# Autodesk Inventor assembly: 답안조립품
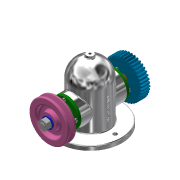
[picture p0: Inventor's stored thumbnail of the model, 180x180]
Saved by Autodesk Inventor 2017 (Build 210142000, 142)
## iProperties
Created: 2019-11
Part Number: 답안조립품
Document SubType Name: Assembly
Designer: 1-15-lg-1
Author: 1-15-lg-1
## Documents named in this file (14)
- C:\Users\1-15-lg-1\Desktop\491104V1023\답안조립품.iam
- C:\Users\1-15-lg-1\Desktop\491104V1023\본체1.ipt
- C:\Users\1-15-lg-1\Desktop\491104V1023\스퍼기어.ipt
- C:\Users\1-15-lg-1\Desktop\491104V1023\오일 실 26 38 8.ipt
- C:\Users\1-15-lg-1\Desktop\491104V1023\와셔 12x24.ipt
- C:\Users\1-15-lg-1\Desktop\491104V1023\축.ipt
- C:\Users\1-15-lg-1\Desktop\491104V1023\커버.ipt
- C:\Users\1-15-lg-1\Desktop\491104V1023\키 5x5x12.ipt
- C:\Users\1-15-lg-1\Desktop\491104V1023\볼트 M4.ipt
- C:\Users\1-15-lg-1\Desktop\491104V1023\부시.ipt
- C:\Users\1-15-lg-1\Desktop\491104V1023\너트 M12x1.25.ipt
- C:\Users\1-15-lg-1\Desktop\491104V1023\베어링 6203.ipt
- C:\Users\1-15-lg-1\Desktop\491104V1023\V-벨트풀리.ipt
- V-벨트풀리.ipt
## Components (1 placed, 1 different names)
1. V-벨트풀리:1 — Mate:17, Mate:18, Mate:19, Mate:24
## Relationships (4: Mate 4)
- Mate:17: V-벨트풀리:1
- Mate:18: V-벨트풀리:1
- Mate:19: V-벨트풀리:1
- Mate:24: V-벨트풀리:1
